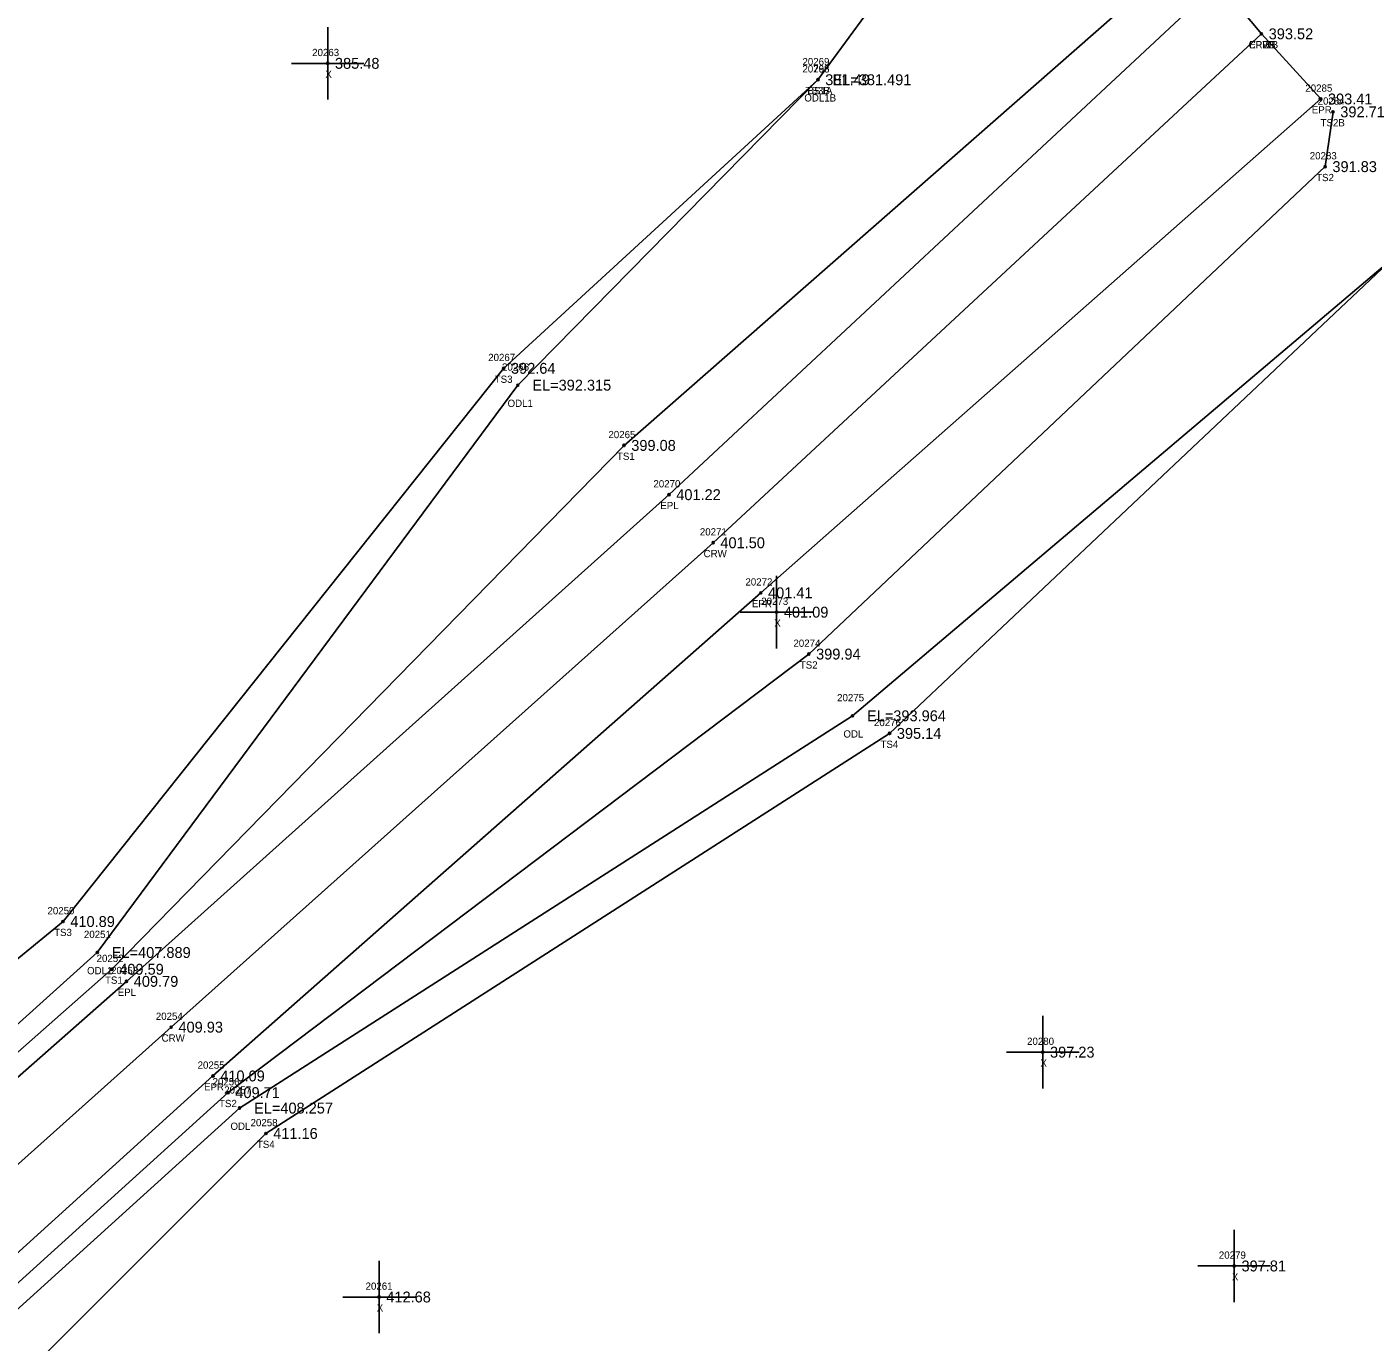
# Model space of a CAD drawing. Extents: x 2116373 to 2118139, y 979529 to 981026.
# Drawn here: x 2117156.4 to 2117341.9, y 979946 to 980127.3 of the extents above; entities that cross this region are included whole.
import ezdxf

# ---------------------------------------------------------------- set-up
doc = ezdxf.new("R2010")
doc.units = 0
for name, color, linetype in [('RD_DTM_BkLn1', 7, 'Continuous'), ('RD_DTM_BkLn2', 7, 'Continuous'), ('RD_DTM_BkLn_txCode', 7, 'Continuous'), ('RD_EX_H2O', 7, 'Continuous'), ('RD_EX_H2O_txCode', 7, 'Continuous'), ('RD_EX_Misc', 7, 'Continuous'), ('RD_EX_Misc_txCode', 7, 'Continuous'), ('RD_EX_Road', 7, 'Continuous'), ('RD_EX_Road_txCode', 7, 'Continuous'), ('RD_EX_TX_H2O_ELEV', 7, 'Continuous'), ('RD_EX_TX_Misc_ELEV', 7, 'Continuous'), ('RD_EX_TX_Road_ELEV', 7, 'Continuous'), ('RD_HC_Survey_ELEV', 7, 'Continuous'), ('RD_HC_Survey_txCode', 7, 'Continuous'), ('RD_SMD_Locator', 7, 'Continuous')]:
    doc.layers.add(name, color=color, linetype=linetype)

msp = doc.modelspace()

# ---------------------------------------------------------------- linework, layer by layer
at = {"layer": 'RD_DTM_BkLn1'}
msp.add_lwpolyline([(2116414.21, 979630.19), (2116468.62, 979643.23), (2116521.45, 979653.6), (2116618.87, 979670.38), (2116668.4, 979680.7), (2116717.3, 979694.48), (2116764.56, 979711.13), (2116810.15, 979729.38), (2116856.49, 979749.81), (2116900.74, 979773.15), (2116944.03, 979798.93), (2116982.75, 979824.6), (2117026.56, 979857.02), (2117064.34, 979888.81), (2117101.78, 979922.69), (2117176.3, 979989.4), (2117250.99, 980056.19), (2117326.56, 980126.36)], dxfattribs=at)
at = {"layer": 'RD_DTM_BkLn2'}
for points in [[(2117265.44, 980120.03), (2117282.69, 980143.6), (2117303.47, 980157.54)], [(2116410.78, 979641.79), (2116465.45, 979654.97), (2116518.83, 979664.89), (2116614.96, 979683.75), (2116663.75, 979692.58), (2116713.02, 979705.22), (2116760.07, 979721.97), (2116804.88, 979741.47), (2116850.79, 979761.38), (2116894.83, 979783.88), (2116937.98, 979807.44), (2116977.39, 979833.6), (2117020.56, 979865.29), (2117056.86, 979896.38), (2117094.29, 979932.2), (2117168.14, 979997.38), (2117238.71, 980069.61), (2117312.33, 980134.21), (2117318.43, 980135.16)], [(2116408.48, 979653.74), (2116461.38, 979665.42), (2116520.7, 979678.48), (2116616.28, 979695.74), (2116661.37, 979703.79), (2116711.18, 979715.21), (2116757.77, 979732.03), (2116802.04, 979749.54), (2116847.76, 979769.63), (2116889.13, 979795.82), (2116931.32, 979820.72), (2116972.01, 979847.71), (2117009.67, 979877.33), (2117051.05, 979910.18), (2117086.71, 979942.74), (2117161.4, 980003.96), (2117222.13, 980080.24), (2117265.44, 980120.03)], [(2116417.57, 979618.2), (2116471.29, 979630.11), (2116523.91, 979640.31), (2116563.87, 979646.21), (2116622.92, 979650.9), (2116673.37, 979660.68), (2116721.38, 979672.44), (2116775.31, 979687.3), (2116820.23, 979708.52), (2116865.35, 979734.51), (2116907.21, 979760.29), (2116934.42, 979772.82), (2116951.5, 979788.78), (2116990.39, 979814.35), (2117033.97, 979847.22), (2117071.26, 979879.46), (2117111.32, 979914.45), (2117184.14, 979980.37), (2117264.18, 980040.84), (2117335.34, 980108.05), (2117336.43, 980115.6)], [(2116934.42, 979772.82), (2116956.11, 979780.15), (2116996.15, 979805.42), (2117040.3, 979838.56), (2117080.53, 979868.79), (2117120.95, 979906.28), (2117189.36, 979974.74), (2117275.31, 980029.9), (2117344.8, 980095.54)]]:
    msp.add_lwpolyline(points, dxfattribs=at)
at = {"layer": 'RD_EX_H2O'}
for points in [[(2116411.09, 979644.42), (2116463.93, 979657.73), (2116517.88, 979668.38), (2116615.09, 979686.35), (2116663.35, 979695.16), (2116711.62, 979708.91), (2116758.49, 979726.13), (2116778.25, 979736.27), (2116803.5, 979744.47), (2116849.89, 979764.23), (2116894.14, 979786.32), (2116936.31, 979809.39), (2116976.21, 979834.9), (2117018.41, 979867.86), (2117054.24, 979898.91), (2117093.35, 979934.14), (2117166.11, 979999.69), (2117224.07, 980077.92), (2117265.44, 980120.03)], [(2116934.42, 979772.82), (2116952.72, 979786.01), (2116992.31, 979812.05), (2117036.21, 979845.2), (2117073.01, 979877), (2117113.79, 979913.05), (2117185.72, 979978.24), (2117270.2, 980032.33), (2117344.8, 980095.54)]]:
    msp.add_lwpolyline(points, dxfattribs=at)
at = {"layer": 'RD_EX_Misc'}
for p, q in [((2117197.87, 980117.29), (2117197.87, 980127.29)), ((2117192.87, 980122.29), (2117202.87, 980122.29)), ((2117259.74, 980041.62), (2117259.74, 980051.62)), ((2117254.74, 980046.62), (2117264.74, 980046.62)), ((2117296.42, 979980.95), (2117296.42, 979990.95)), ((2117291.42, 979985.95), (2117301.42, 979985.95)), ((2117322.81, 979951.47), (2117322.81, 979961.47)), ((2117204.95, 979947.19), (2117204.95, 979957.19)), ((2117317.81, 979956.47), (2117327.81, 979956.47)), ((2117199.95, 979952.19), (2117209.95, 979952.19))]:
    msp.add_line(p, q, dxfattribs=at)
at = {"layer": 'RD_EX_Road'}
for points in [[(2116412.2, 979638.84), (2116468.17, 979651.36), (2116519.2, 979662.5), (2116617.24, 979678.85), (2116665.51, 979689.1), (2116714.23, 979702.46), (2116761.42, 979719.35), (2116806.99, 979737.42), (2116852.23, 979758.11), (2116896.57, 979780.91), (2116939.1, 979805.52), (2116978.46, 979832.1), (2117021.29, 979863.87), (2117058.15, 979895.61), (2117096.06, 979930.47), (2117170.14, 979995.71), (2117244.91, 980062.82), (2117320.63, 980133.49), (2117326.56, 980126.36)], [(2116416.36, 979621.21), (2116470.51, 979634.11), (2116523.97, 979644.68), (2116620.55, 979661.21), (2116670.7, 979671.96), (2116720.65, 979685.84), (2116767.66, 979702.22), (2116814.07, 979721.02), (2116860.35, 979742.3), (2116904.9, 979765.18), (2116949.06, 979791.19), (2116988.09, 979817.15), (2117031.94, 979849.78), (2117069.79, 979881.53), (2117108.89, 979916.38), (2117182.06, 979982.67), (2117257.56, 980049.29), (2117334.73, 980117.38), (2117326.56, 980126.36)]]:
    msp.add_lwpolyline(points, dxfattribs=at)
at = {"layer": 'RD_SMD_Locator'}
for centre in [(2117326.56, 980126.36), (2117326.56, 980126.36), (2117326.56, 980126.36), (2117197.87, 980122.29), (2117265.44, 980120.03), (2117265.44, 980120.03), (2117265.44, 980120.03), (2117334.73, 980117.38), (2117336.43, 980115.6), (2117335.34, 980108.05), (2117222.13, 980080.24), (2117224.07, 980077.92), (2117238.71, 980069.61), (2117244.91, 980062.82), (2117250.99, 980056.19), (2117257.56, 980049.29), (2117259.74, 980046.62), (2117264.18, 980040.84), (2117270.2, 980032.33), (2117275.31, 980029.9), (2117161.4, 980003.96), (2117166.11, 979999.69), (2117168.14, 979997.38), (2117170.14, 979995.71), (2117176.3, 979989.4), (2117296.42, 979985.95), (2117182.06, 979982.67), (2117184.14, 979980.37), (2117185.72, 979978.24), (2117189.36, 979974.74), (2117322.81, 979956.47), (2117204.95, 979952.19)]:
    msp.add_circle(centre, 0.15, dxfattribs=at)

# ---------------------------------------------------------------- texts
at = {"layer": 'RD_DTM_BkLn_txCode'}
for s, p in [('20268', (2117263.3, 980121.03)), ('20796', (2117263.3, 980121.03)), ('TS3B', (2117263.73, 980118.03)), ('BS1A', (2117264.01, 980118.03)), ('20284', (2117334.31, 980116.6)), ('TS2B', (2117334.71, 980113.6)), ('20283', (2117333.22, 980109.05)), ('TS2', (2117334.1, 980106.05)), ('20267', (2117219.99, 980081.24)), ('TS3', (2117220.89, 980078.24)), ('20265', (2117236.56, 980070.61)), ('TS1', (2117237.74, 980067.61)), ('20274', (2117262.06, 980041.84)), ('TS2', (2117262.94, 980038.84)), ('20276', (2117273.16, 980030.9)), ('TS4', (2117274.06, 980027.9)), ('20250', (2117159.25, 980004.96)), ('TS3', (2117160.16, 980001.96)), ('20252', (2117166.02, 979998.38)), ('TS1', (2117167.18, 979995.38)), ('20256', (2117182, 979981.37)), ('TS2', (2117182.89, 979978.37)), ('20258', (2117187.24, 979975.74)), ('TS4', (2117188.11, 979972.74))]:
    msp.add_text(s, height=1, dxfattribs=at).set_placement(p)
at = {"layer": 'RD_EX_H2O_txCode'}
for s, p in [('20269', (2117263.3, 980122.03)), ('ODL1B', (2117263.56, 980117.03)), ('20266', (2117221.9, 980079.92)), ('ODL1', (2117222.66, 980074.92)), ('20275', (2117268.08, 980034.33)), ('ODL', (2117268.95, 980029.33)), ('20251', (2117164.27, 980001.69)), ('ODL1', (2117164.7, 979996.69)), ('20257', (2117183.6, 979980.24)), ('ODL', (2117184.47, 979975.24))]:
    msp.add_text(s, height=1, dxfattribs=at).set_placement(p)
at = {"layer": 'RD_EX_Misc_txCode'}
for s, p in [('20263', (2117195.73, 980123.29)), ('X', (2117197.55, 980120.29)), ('20273', (2117257.62, 980047.62)), ('X', (2117259.42, 980044.62)), ('20280', (2117294.26, 979986.95)), ('X', (2117296.1, 979983.95)), ('20279', (2117320.69, 979957.47)), ('20261', (2117203.09, 979953.19)), ('X', (2117322.49, 979954.47)), ('X', (2117204.63, 979950.19))]:
    msp.add_text(s, height=1, dxfattribs=at).set_placement(p)
at = {"layer": 'RD_EX_Road_txCode'}
for s, p in [('EPRB', (2117324.86, 980124.36)), ('EPLB', (2117324.89, 980124.36)), ('20285', (2117332.61, 980118.38)), ('EPR', (2117333.5, 980115.38)), ('20270', (2117242.76, 980063.82)), ('EPL', (2117243.71, 980060.82)), ('20272', (2117255.44, 980050.29)), ('EPR', (2117256.33, 980047.29)), ('20253', (2117168.02, 979996.71)), ('EPL', (2117168.93, 979993.71)), ('20255', (2117179.94, 979983.67)), ('EPR', (2117180.83, 979980.67))]:
    msp.add_text(s, height=1, dxfattribs=at).set_placement(p)
at = {"layer": 'RD_EX_TX_H2O_ELEV'}
for s, p in [('EL=381.491', (2117267.44, 980119.28)), ('EL=392.315', (2117226.07, 980077.17)), ('EL=393.964', (2117272.2, 980031.58)), ('EL=407.889', (2117168.11, 979998.94)), ('EL=408.257', (2117187.72, 979977.49))]:
    msp.add_text(s, height=1.5, dxfattribs=at).set_placement(p)
at = {"layer": 'RD_EX_TX_Misc_ELEV'}
for s, p in [('385.48', (2117198.87, 980121.54)), ('381.49', (2117266.44, 980119.28)), ('381.49', (2117266.44, 980119.28)), ('392.71', (2117337.43, 980114.85)), ('391.83', (2117336.34, 980107.3)), ('392.64', (2117223.13, 980079.49)), ('399.08', (2117239.71, 980068.86)), ('401.09', (2117260.74, 980045.87)), ('399.94', (2117265.18, 980040.09)), ('395.14', (2117276.31, 980029.15)), ('410.89', (2117162.4, 980003.21)), ('409.59', (2117169.14, 979996.63)), ('397.23', (2117297.42, 979985.2)), ('409.71', (2117185.14, 979979.62)), ('411.16', (2117190.36, 979973.99)), ('397.81', (2117323.81, 979955.72)), ('412.68', (2117205.95, 979951.44))]:
    msp.add_text(s, height=1.5, dxfattribs=at).set_placement(p)
at = {"layer": 'RD_EX_TX_Road_ELEV'}
for s, p in [('393.52', (2117327.56, 980125.61)), ('393.52', (2117327.56, 980125.61)), ('393.41', (2117335.73, 980116.63)), ('401.22', (2117245.91, 980062.07)), ('401.41', (2117258.56, 980048.54)), ('409.79', (2117171.14, 979994.96)), ('410.09', (2117183.06, 979981.92))]:
    msp.add_text(s, height=1.5, dxfattribs=at).set_placement(p)
at = {"layer": 'RD_HC_Survey_ELEV'}
for s, p in [('393.52', (2117327.56, 980125.61)), ('401.50', (2117251.99, 980055.44)), ('409.93', (2117177.3, 979988.65))]:
    msp.add_text(s, height=1.5, dxfattribs=at).set_placement(p)
at = {"layer": 'RD_HC_Survey_txCode'}
for s, p in [('CRWB', (2117324.78, 980124.36)), ('20271', (2117249.16, 980057.19)), ('CRW', (2117249.68, 980054.19)), ('20254', (2117174.18, 979990.4)), ('CRW', (2117174.98, 979987.4))]:
    msp.add_text(s, height=1, dxfattribs=at).set_placement(p)

doc.saveas('drawing.dxf')
